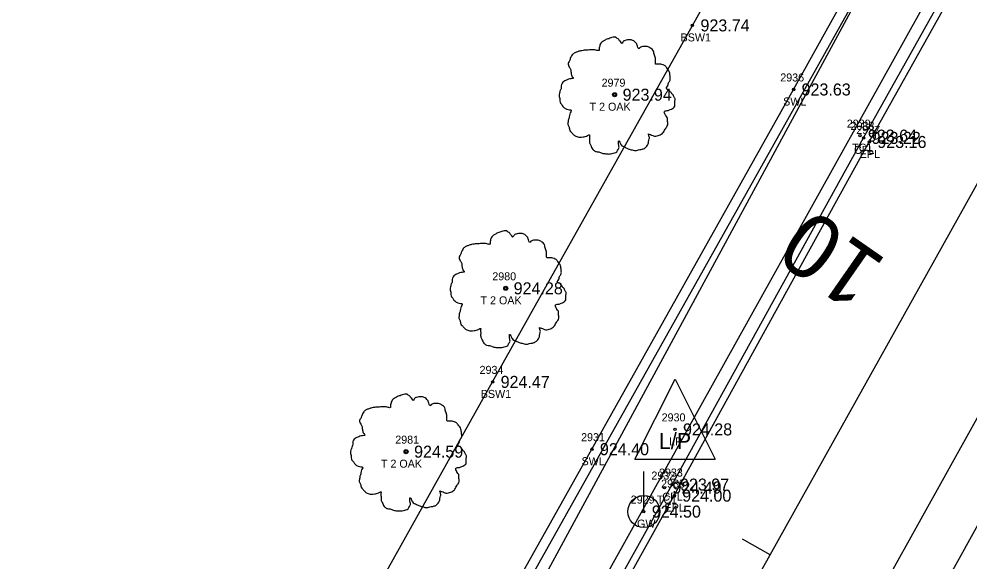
# Model space of a CAD drawing. Extents: x 1575382 to 1578175, y 1099175 to 1101955.
# Drawn here: x 1576923.3 to 1577042, y 1100636.3 to 1100704 of the extents above; entities that cross this region are included whole.
import ezdxf

# ---------------------------------------------------------------- set-up
doc = ezdxf.new("R2010")
doc.units = 0
for name, color, linetype in [('RD_EX_Conc', 7, 'Continuous'), ('RD_EX_Conc_txCode', 7, 'Continuous'), ('RD_EX_Road', 7, 'Continuous'), ('RD_EX_Road_txCode', 7, 'Continuous'), ('RD_EX_TX_Conc_ELEV', 7, 'Continuous'), ('RD_EX_TX_Road_ELEV', 7, 'Continuous'), ('RD_EX_TX_UT_ELEV', 7, 'Continuous'), ('RD_EX_TX_VEG_ELEV', 7, 'Continuous'), ('RD_EX_UT', 7, 'Continuous'), ('RD_EX_UT_txCode', 7, 'Continuous'), ('RD_EX_VEG', 7, 'Continuous'), ('RD_EX_VEG_txCode', 7, 'Continuous'), ('RD_HC_Cl', 7, 'Continuous'), ('RD_HC_Data_Tic', 7, 'Continuous'), ('RD_HC_TX_Sta50', 7, 'Continuous'), ('RD_SMD_Locator', 7, 'Continuous')]:
    doc.layers.add(name, color=color, linetype=linetype)

msp = doc.modelspace()

# ---------------------------------------------------------------- linework, layer by layer
at = {"layer": 'RD_EX_Conc'}
for points in [[(1576915.51, 1100485.43), (1576931.67, 1100514.72), (1576963.55, 1100571.7), (1576980.25, 1100601.73), (1577004.87, 1100645.93), (1577028.8, 1100689.21), (1577055.24, 1100736.45), (1577057.45, 1100744.79), (1577058.3, 1100753.83), (1577056.52, 1100760.31), (1577053.21, 1100754.37)], [(1576891.15, 1100493), (1576919.81, 1100523.92), (1576927.44, 1100533.74), (1576954.89, 1100579.32), (1576970.59, 1100607.1), (1576994.86, 1100650.35), (1577020.05, 1100695.25), (1577043.02, 1100736.52), (1577053.21, 1100754.37)], [(1576877.92, 1100500.23), (1576907.33, 1100532.14), (1576916.05, 1100543.22), (1576941.93, 1100586.45), (1576957.84, 1100614.79), (1576982.46, 1100658.75), (1577007.42, 1100703.25), (1577021.88, 1100729.08)], [(1576925.28, 1100434.6), (1576931.32, 1100441.65), (1576943.72, 1100456.06), (1576959.8, 1100485.15), (1576962.79, 1100490.55), (1576976.91, 1100516.3), (1576979.99, 1100521.81), (1576994.08, 1100547.41), (1577013.9, 1100582.65), (1577028.01, 1100607.52), (1577031.93, 1100618.57), (1577033.8, 1100624.22), (1577052.4, 1100657.66), (1577055.15, 1100662.64), (1577085.17, 1100716.01)]]:
    msp.add_lwpolyline(points, dxfattribs=at)
at = {"layer": 'RD_EX_Road'}
for points in [[(1576898.13, 1100449.6), (1576900.3, 1100453.32), (1576908.44, 1100470.19), (1576911.63, 1100476.81), (1576915.14, 1100482.86), (1576932.49, 1100514.03), (1576964.32, 1100571.23), (1576981.09, 1100601.29), (1577005.14, 1100644.55), (1577029.51, 1100688.7), (1577055.93, 1100735.94), (1577058.21, 1100744.65), (1577059.15, 1100754.07), (1577057.45, 1100760.72), (1577053.13, 1100767.88), (1577044.53, 1100776.69), (1577044.53, 1100776.69), (1577000.54, 1100813.12), (1576959.68, 1100843.4), (1576921.64, 1100879.47), (1576887.69, 1100919.8), (1576859.54, 1100961.84), (1576835.4, 1101008.92), (1576817.26, 1101055.71)], [(1576918.43, 1100436.45), (1576919.69, 1100438.1), (1576919.21, 1100438.45), (1576924.62, 1100446.41), (1576935.15, 1100461.4), (1576954.41, 1100495.42), (1576968.8, 1100521.52), (1576985.92, 1100552.3), (1577005.62, 1100587.42), (1577028.14, 1100627.58), (1577046.67, 1100660.87), (1577078.76, 1100718.33)]]:
    msp.add_lwpolyline(points, dxfattribs=at)
at = {"layer": 'RD_EX_UT'}
for p, q in [((1577000.24, 1100649.1), (1577005.24, 1100659.1)), ((1577005.24, 1100659.1), (1577010.24, 1100649.1)), ((1577000.24, 1100649.1), (1577010.24, 1100649.1)), ((1577001.34, 1100642.56), (1577001.34, 1100647.56))]:
    msp.add_line(p, q, dxfattribs=at)
msp.add_lwpolyline([(1576697.98, 1101074.32), (1577079.49, 1100801.52), (1576931.93, 1100529.3), (1577183.5, 1100413.67)], dxfattribs=at)
msp.add_circle((1577001.34, 1100642.56), 2, dxfattribs=at)
at = {"layer": 'RD_EX_VEG'}
msp.add_lwpolyline([(1576914.19, 1100486.82), (1576910.45, 1100488.95), (1576907.96, 1100484.96), (1576892.65, 1100493.17), (1576920.35, 1100523.24), (1576956.05, 1100578.76), (1577056.18, 1100757.22), (1577053.86, 1100737.22), (1576914.19, 1100486.82)], dxfattribs=at)
for centre, radius in [((1576997.7, 1100694.6), 0.25), ((1576997.69, 1100694.58), 0.0001), ((1576984.09, 1100670.43), 0.25), ((1576984.07, 1100670.41), 0.0001), ((1576971.65, 1100650.04), 0.25), ((1576971.63, 1100650.02), 0.0001)]:
    msp.add_circle(centre, radius, dxfattribs=at)
for points in [[(1576997.83, 1100701.77), (1576997.53, 1100701.79), (1576997.21, 1100701.69), (1576996.96, 1100701.59), (1576996.73, 1100701.52), (1576996.51, 1100701.42), (1576996.21, 1100701.24), (1576995.98, 1100701.04), (1576995.86, 1100700.79), (1576995.81, 1100700.57), (1576995.76, 1100700.3), (1576995.76, 1100700.12), (1576995.63, 1100700.1), (1576995.48, 1100700.12), (1576995.23, 1100700.2), (1576994.98, 1100700.2), (1576994.73, 1100700.2), (1576994.38, 1100700.17), (1576994.03, 1100700.17), (1576993.76, 1100700.12), (1576993.43, 1100700.07), (1576993.06, 1100699.95), (1576992.71, 1100699.82), (1576992.41, 1100699.57), (1576992.16, 1100699.1), (1576992.04, 1100698.75), (1576991.89, 1100698.5), (1576992.04, 1100698.05), (1576992.21, 1100697.7), (1576992.24, 1100697.5), (1576992.31, 1100697.07), (1576992.41, 1100696.85), (1576992.54, 1100696.65), (1576992.46, 1100696.62), (1576992.09, 1100696.57), (1576991.79, 1100696.47), (1576991.36, 1100696.25), (1576991.14, 1100696.02), (1576991.04, 1100695.7), (1576991.01, 1100695.35), (1576990.91, 1100695.15), (1576990.84, 1100694.87), (1576990.81, 1100694.8), (1576990.76, 1100694.47), (1576990.86, 1100694.02), (1576990.89, 1100693.67), (1576991.01, 1100693.45), (1576991.16, 1100693.27), (1576991.34, 1100693.02), (1576991.74, 1100692.8), (1576992.06, 1100692.7), (1576992.26, 1100692.67), (1576992.09, 1100692.17), (1576992.04, 1100691.82), (1576991.91, 1100691.42), (1576991.91, 1100691.35), (1576991.86, 1100690.87), (1576992.01, 1100690.55), (1576992.09, 1100690.17), (1576992.26, 1100689.95), (1576992.54, 1100689.65), (1576992.86, 1100689.42), (1576993.36, 1100689.3), (1576993.76, 1100689.32), (1576994.33, 1100689.5), (1576994.58, 1100689.57), (1576994.56, 1100689.4), (1576994.58, 1100689.02), (1576994.58, 1100688.6), (1576994.73, 1100688.28), (1576994.83, 1100688), (1576994.98, 1100687.75), (1576995.31, 1100687.53), (1576995.71, 1100687.45), (1576996.13, 1100687.3), (1576996.58, 1100687.23), (1576997.08, 1100687.2), (1576997.68, 1100687.35), (1576997.96, 1100687.48), (1576998.06, 1100687.65), (1576998.26, 1100688.03), (1576998.21, 1100688.25), (1576998.23, 1100688.85), (1576998.33, 1100688.68), (1576998.51, 1100688.33), (1576999.01, 1100688.03), (1576999.41, 1100687.85), (1576999.88, 1100687.7), (1577000.18, 1100687.63), (1577000.66, 1100687.7), (1577001.03, 1100687.78), (1577001.41, 1100687.9), (1577001.71, 1100688.18), (1577001.88, 1100688.45), (1577001.93, 1100688.73), (1577002.01, 1100689.1), (1577002.06, 1100689.27)], [(1577002.06, 1100689.27), (1577001.98, 1100689.45), (1577001.93, 1100689.7), (1577002.01, 1100689.67), (1577002.18, 1100689.62), (1577002.46, 1100689.5), (1577002.68, 1100689.42), (1577003.01, 1100689.45), (1577003.28, 1100689.55), (1577003.73, 1100689.82), (1577004.01, 1100690.3), (1577004.28, 1100690.7), (1577004.35, 1100691.02), (1577004.3, 1100691.25), (1577004.28, 1100691.75), (1577004.08, 1100692), (1577004.03, 1100692.12), (1577003.93, 1100692.52), (1577004.01, 1100692.57), (1577004.28, 1100692.62), (1577004.65, 1100692.75), (1577004.93, 1100692.87), (1577005.15, 1100693.05), (1577005.23, 1100693.27), (1577005.2, 1100693.67), (1577005.25, 1100694.07), (1577005.18, 1100694.22), (1577005.08, 1100694.37), (1577005, 1100694.57), (1577004.85, 1100694.72), (1577004.75, 1100694.87), (1577004.65, 1100694.97), (1577004.53, 1100695.12), (1577004.35, 1100695.25), (1577004.2, 1100695.3), (1577004.15, 1100695.45), (1577004.3, 1100695.65), (1577004.35, 1100695.75), (1577004.38, 1100695.97), (1577004.6, 1100696.32), (1577004.65, 1100696.72), (1577004.6, 1100697.15), (1577004.55, 1100697.42), (1577004.4, 1100697.7), (1577004.2, 1100697.95), (1577004.08, 1100698.12), (1577003.91, 1100698.25), (1577003.58, 1100698.37), (1577003.33, 1100698.42), (1577002.98, 1100698.42), (1577002.78, 1100698.47), (1577002.81, 1100698.52), (1577002.81, 1100698.67), (1577002.81, 1100698.95), (1577002.73, 1100699.4), (1577002.58, 1100699.9), (1577002.58, 1100699.92), (1577002.48, 1100700.17), (1577002.26, 1100700.37), (1577002.08, 1100700.47), (1577001.88, 1100700.59), (1577001.63, 1100700.62), (1577001.33, 1100700.62), (1577001.06, 1100700.57), (1577000.86, 1100700.47), (1577000.68, 1100700.35), (1577000.61, 1100700.49), (1577000.51, 1100700.79), (1577000.46, 1100700.94), (1577000.31, 1100701.12), (1577000.08, 1100701.32), (1576999.63, 1100701.44), (1576999.01, 1100701.37), (1576998.71, 1100701.17), (1576998.56, 1100700.99), (1576998.51, 1100701.12), (1576998.31, 1100701.32), (1576998.21, 1100701.49), (1576998.03, 1100701.62), (1576997.88, 1100701.72), (1576997.78, 1100701.77)], [(1576984.22, 1100677.6), (1576983.92, 1100677.62), (1576983.59, 1100677.52), (1576983.34, 1100677.42), (1576983.12, 1100677.35), (1576982.89, 1100677.25), (1576982.59, 1100677.07), (1576982.37, 1100676.87), (1576982.24, 1100676.62), (1576982.19, 1100676.4), (1576982.14, 1100676.12), (1576982.14, 1100675.95), (1576982.02, 1100675.92), (1576981.87, 1100675.95), (1576981.62, 1100676.02), (1576981.37, 1100676.02), (1576981.12, 1100676.02), (1576980.77, 1100676), (1576980.42, 1100676), (1576980.15, 1100675.95), (1576979.82, 1100675.9), (1576979.45, 1100675.77), (1576979.1, 1100675.65), (1576978.8, 1100675.4), (1576978.55, 1100674.92), (1576978.42, 1100674.57), (1576978.27, 1100674.32), (1576978.42, 1100673.87), (1576978.6, 1100673.52), (1576978.62, 1100673.32), (1576978.7, 1100672.9), (1576978.8, 1100672.67), (1576978.92, 1100672.47), (1576978.85, 1100672.45), (1576978.47, 1100672.4), (1576978.17, 1100672.3), (1576977.75, 1100672.08), (1576977.52, 1100671.85), (1576977.42, 1100671.53), (1576977.4, 1100671.18), (1576977.3, 1100670.98), (1576977.22, 1100670.7), (1576977.2, 1100670.63), (1576977.15, 1100670.3), (1576977.25, 1100669.85), (1576977.27, 1100669.5), (1576977.4, 1100669.28), (1576977.55, 1100669.1), (1576977.72, 1100668.85), (1576978.12, 1100668.63), (1576978.45, 1100668.53), (1576978.65, 1100668.5), (1576978.47, 1100668), (1576978.42, 1100667.65), (1576978.3, 1100667.25), (1576978.3, 1100667.18), (1576978.25, 1100666.7), (1576978.4, 1100666.38), (1576978.47, 1100666), (1576978.65, 1100665.78), (1576978.92, 1100665.48), (1576979.25, 1100665.25), (1576979.75, 1100665.13), (1576980.15, 1100665.15), (1576980.72, 1100665.33), (1576980.97, 1100665.4), (1576980.95, 1100665.23), (1576980.97, 1100664.85), (1576980.97, 1100664.43), (1576981.12, 1100664.1), (1576981.22, 1100663.83), (1576981.37, 1100663.58), (1576981.7, 1100663.35), (1576982.09, 1100663.28), (1576982.52, 1100663.13), (1576982.97, 1100663.05), (1576983.47, 1100663.03), (1576984.07, 1100663.18), (1576984.34, 1100663.3), (1576984.44, 1100663.48), (1576984.64, 1100663.85), (1576984.59, 1100664.08), (1576984.62, 1100664.68), (1576984.72, 1100664.5), (1576984.89, 1100664.15), (1576985.39, 1100663.85), (1576985.79, 1100663.68), (1576986.27, 1100663.53), (1576986.57, 1100663.45), (1576987.04, 1100663.53), (1576987.42, 1100663.6), (1576987.79, 1100663.73), (1576988.09, 1100664), (1576988.27, 1100664.28), (1576988.32, 1100664.55), (1576988.39, 1100664.93), (1576988.44, 1100665.1)], [(1576988.44, 1100665.1), (1576988.37, 1100665.28), (1576988.32, 1100665.53), (1576988.39, 1100665.5), (1576988.57, 1100665.45), (1576988.84, 1100665.33), (1576989.07, 1100665.25), (1576989.39, 1100665.28), (1576989.67, 1100665.38), (1576990.12, 1100665.65), (1576990.39, 1100666.13), (1576990.67, 1100666.53), (1576990.74, 1100666.85), (1576990.69, 1100667.08), (1576990.67, 1100667.58), (1576990.47, 1100667.83), (1576990.42, 1100667.95), (1576990.32, 1100668.35), (1576990.39, 1100668.4), (1576990.67, 1100668.45), (1576991.04, 1100668.58), (1576991.32, 1100668.7), (1576991.54, 1100668.88), (1576991.62, 1100669.1), (1576991.59, 1100669.5), (1576991.64, 1100669.9), (1576991.57, 1100670.05), (1576991.47, 1100670.2), (1576991.39, 1100670.4), (1576991.24, 1100670.55), (1576991.14, 1100670.7), (1576991.04, 1100670.8), (1576990.92, 1100670.95), (1576990.74, 1100671.08), (1576990.59, 1100671.13), (1576990.54, 1100671.28), (1576990.69, 1100671.48), (1576990.74, 1100671.58), (1576990.77, 1100671.8), (1576990.99, 1100672.15), (1576991.04, 1100672.55), (1576990.99, 1100672.97), (1576990.94, 1100673.25), (1576990.79, 1100673.52), (1576990.59, 1100673.77), (1576990.47, 1100673.95), (1576990.29, 1100674.07), (1576989.97, 1100674.2), (1576989.72, 1100674.25), (1576989.37, 1100674.25), (1576989.17, 1100674.3), (1576989.19, 1100674.35), (1576989.19, 1100674.5), (1576989.19, 1100674.77), (1576989.12, 1100675.22), (1576988.97, 1100675.72), (1576988.97, 1100675.75), (1576988.87, 1100676), (1576988.64, 1100676.2), (1576988.47, 1100676.3), (1576988.27, 1100676.42), (1576988.02, 1100676.45), (1576987.72, 1100676.45), (1576987.44, 1100676.4), (1576987.24, 1100676.3), (1576987.07, 1100676.17), (1576986.99, 1100676.32), (1576986.89, 1100676.62), (1576986.84, 1100676.77), (1576986.69, 1100676.95), (1576986.47, 1100677.15), (1576986.02, 1100677.27), (1576985.39, 1100677.2), (1576985.09, 1100677), (1576984.94, 1100676.82), (1576984.89, 1100676.95), (1576984.69, 1100677.15), (1576984.59, 1100677.32), (1576984.42, 1100677.45), (1576984.27, 1100677.55), (1576984.17, 1100677.6)], [(1576971.78, 1100657.21), (1576971.48, 1100657.23), (1576971.15, 1100657.13), (1576970.9, 1100657.03), (1576970.68, 1100656.96), (1576970.45, 1100656.86), (1576970.15, 1100656.68), (1576969.93, 1100656.48), (1576969.8, 1100656.23), (1576969.75, 1100656.01), (1576969.7, 1100655.73), (1576969.7, 1100655.56), (1576969.58, 1100655.53), (1576969.43, 1100655.56), (1576969.18, 1100655.63), (1576968.93, 1100655.63), (1576968.68, 1100655.63), (1576968.33, 1100655.61), (1576967.98, 1100655.61), (1576967.71, 1100655.56), (1576967.38, 1100655.51), (1576967.01, 1100655.38), (1576966.66, 1100655.26), (1576966.36, 1100655.01), (1576966.11, 1100654.53), (1576965.98, 1100654.18), (1576965.83, 1100653.93), (1576965.98, 1100653.48), (1576966.16, 1100653.13), (1576966.18, 1100652.93), (1576966.26, 1100652.51), (1576966.36, 1100652.29), (1576966.48, 1100652.09), (1576966.41, 1100652.06), (1576966.03, 1100652.01), (1576965.73, 1100651.91), (1576965.31, 1100651.69), (1576965.08, 1100651.46), (1576964.98, 1100651.14), (1576964.96, 1100650.79), (1576964.86, 1100650.59), (1576964.78, 1100650.31), (1576964.76, 1100650.24), (1576964.71, 1100649.91), (1576964.81, 1100649.46), (1576964.83, 1100649.11), (1576964.96, 1100648.89), (1576965.11, 1100648.71), (1576965.28, 1100648.46), (1576965.68, 1100648.24), (1576966.01, 1100648.14), (1576966.21, 1100648.11), (1576966.03, 1100647.61), (1576965.98, 1100647.26), (1576965.86, 1100646.86), (1576965.86, 1100646.79), (1576965.81, 1100646.31), (1576965.96, 1100645.99), (1576966.03, 1100645.61), (1576966.21, 1100645.39), (1576966.48, 1100645.09), (1576966.81, 1100644.86), (1576967.31, 1100644.74), (1576967.71, 1100644.76), (1576968.28, 1100644.94), (1576968.53, 1100645.01), (1576968.5, 1100644.84), (1576968.53, 1100644.46), (1576968.53, 1100644.04), (1576968.68, 1100643.71), (1576968.78, 1100643.44), (1576968.93, 1100643.19), (1576969.25, 1100642.96), (1576969.65, 1100642.89), (1576970.08, 1100642.74), (1576970.53, 1100642.66), (1576971.03, 1100642.64), (1576971.63, 1100642.79), (1576971.9, 1100642.91), (1576972, 1100643.09), (1576972.2, 1100643.46), (1576972.15, 1100643.69), (1576972.18, 1100644.29), (1576972.28, 1100644.11), (1576972.45, 1100643.76), (1576972.95, 1100643.46), (1576973.35, 1100643.29), (1576973.83, 1100643.14), (1576974.13, 1100643.06), (1576974.6, 1100643.14), (1576974.98, 1100643.21), (1576975.35, 1100643.34), (1576975.65, 1100643.61), (1576975.83, 1100643.89), (1576975.88, 1100644.16), (1576975.95, 1100644.54), (1576976, 1100644.71)], [(1576976, 1100644.71), (1576975.93, 1100644.89), (1576975.88, 1100645.14), (1576975.95, 1100645.11), (1576976.13, 1100645.06), (1576976.4, 1100644.94), (1576976.63, 1100644.86), (1576976.95, 1100644.89), (1576977.23, 1100644.99), (1576977.68, 1100645.26), (1576977.95, 1100645.74), (1576978.23, 1100646.14), (1576978.3, 1100646.46), (1576978.25, 1100646.69), (1576978.23, 1100647.19), (1576978.03, 1100647.44), (1576977.98, 1100647.56), (1576977.88, 1100647.96), (1576977.95, 1100648.01), (1576978.23, 1100648.06), (1576978.6, 1100648.19), (1576978.88, 1100648.31), (1576979.1, 1100648.49), (1576979.17, 1100648.71), (1576979.15, 1100649.11), (1576979.2, 1100649.51), (1576979.13, 1100649.66), (1576979.03, 1100649.81), (1576978.95, 1100650.01), (1576978.8, 1100650.16), (1576978.7, 1100650.31), (1576978.6, 1100650.41), (1576978.48, 1100650.56), (1576978.3, 1100650.69), (1576978.15, 1100650.74), (1576978.1, 1100650.89), (1576978.25, 1100651.09), (1576978.3, 1100651.19), (1576978.33, 1100651.41), (1576978.55, 1100651.76), (1576978.6, 1100652.16), (1576978.55, 1100652.59), (1576978.5, 1100652.86), (1576978.35, 1100653.13), (1576978.15, 1100653.38), (1576978.03, 1100653.56), (1576977.85, 1100653.68), (1576977.53, 1100653.81), (1576977.28, 1100653.86), (1576976.93, 1100653.86), (1576976.73, 1100653.91), (1576976.75, 1100653.96), (1576976.75, 1100654.11), (1576976.75, 1100654.38), (1576976.68, 1100654.83), (1576976.53, 1100655.33), (1576976.53, 1100655.36), (1576976.43, 1100655.61), (1576976.2, 1100655.81), (1576976.03, 1100655.91), (1576975.83, 1100656.03), (1576975.58, 1100656.06), (1576975.28, 1100656.06), (1576975, 1100656.01), (1576974.8, 1100655.91), (1576974.63, 1100655.78), (1576974.55, 1100655.93), (1576974.45, 1100656.23), (1576974.4, 1100656.38), (1576974.25, 1100656.56), (1576974.03, 1100656.76), (1576973.58, 1100656.88), (1576972.95, 1100656.81), (1576972.65, 1100656.61), (1576972.5, 1100656.43), (1576972.45, 1100656.56), (1576972.25, 1100656.76), (1576972.15, 1100656.93), (1576971.98, 1100657.06), (1576971.83, 1100657.16), (1576971.73, 1100657.21)]]:
    msp.add_spline(points, degree=3, dxfattribs=at)
at = {"layer": 'RD_HC_Cl'}
msp.add_line((1576888.29, 1100406.32), (1577092.18, 1100771.63), dxfattribs=at)
at = {"layer": 'RD_HC_Data_Tic'}
msp.add_line((1577017.14, 1100637.18), (1577013.65, 1100639.13), dxfattribs=at)
at = {"layer": 'RD_SMD_Locator'}
for centre in [(1577007.42, 1100703.25), (1577020.05, 1100695.25), (1576997.7, 1100694.6), (1577028.33, 1100689.49), (1577028.8, 1100689.21), (1577029.51, 1100688.7), (1576984.09, 1100670.43), (1576982.46, 1100658.75), (1577005.24, 1100652.82), (1576971.65, 1100650.04), (1576994.86, 1100650.35), (1577003.92, 1100645.56), (1577004.87, 1100645.93), (1577005.14, 1100644.55), (1577001.34, 1100642.56)]:
    msp.add_circle(centre, 0.15, dxfattribs=at)

# ---------------------------------------------------------------- texts
at = {"layer": 'RD_EX_Conc_txCode'}
for s, p in [('BSW1', (1577005.94, 1100701.25)), ('2936', (1577018.39, 1100696.25)), ('SWL', (1577018.75, 1100693.25)), ('2939', (1577026.7, 1100690.49)), ('2938', (1577027.17, 1100690.21)), ('TC1', (1577027.37, 1100687.49)), ('CFL', (1577027.6, 1100687.21)), ('2934', (1576980.83, 1100659.75)), ('BSW1', (1576980.98, 1100656.75)), ('2931', (1576993.51, 1100651.35)), ('SWL', (1576993.57, 1100648.35)), ('2932', (1577002.29, 1100646.56)), ('2933', (1577003.24, 1100646.93)), ('TC1', (1577002.96, 1100643.56)), ('CFL', (1577003.66, 1100643.93))]:
    msp.add_text(s, height=1, dxfattribs=at).set_placement(p)
at = {"layer": 'RD_EX_Road_txCode'}
for s, p in [('2937', (1577027.88, 1100689.7)), ('EPL', (1577028.31, 1100686.7)), ('2935', (1577003.51, 1100645.55)), ('EPL', (1577003.94, 1100642.55))]:
    msp.add_text(s, height=1, dxfattribs=at).set_placement(p)
at = {"layer": 'RD_EX_TX_Conc_ELEV'}
for s, p in [('923.74', (1577008.42, 1100702.5)), ('923.63', (1577021.05, 1100694.5)), ('923.64', (1577029.33, 1100688.74)), ('923.22', (1577029.8, 1100688.46)), ('924.47', (1576983.46, 1100658)), ('924.40', (1576995.86, 1100649.6)), ('924.49', (1577004.92, 1100644.81)), ('923.97', (1577005.87, 1100645.18))]:
    msp.add_text(s, height=1.5, dxfattribs=at).set_placement(p)
at = {"layer": 'RD_EX_TX_Road_ELEV'}
for s, p in [('923.16', (1577030.51, 1100687.95)), ('924.00', (1577006.14, 1100643.8))]:
    msp.add_text(s, height=1.5, dxfattribs=at).set_placement(p)
at = {"layer": 'RD_EX_TX_UT_ELEV'}
for s, p in [('924.28', (1577006.24, 1100652.07)), ('924.50', (1577002.34, 1100641.81))]:
    msp.add_text(s, height=1.5, dxfattribs=at).set_placement(p)
at = {"layer": 'RD_EX_TX_VEG_ELEV'}
for s, p in [('923.94', (1576998.7, 1100693.85)), ('924.28', (1576985.09, 1100669.68)), ('924.59', (1576972.65, 1100649.29))]:
    msp.add_text(s, height=1.5, dxfattribs=at).set_placement(p)
at = {"layer": 'RD_EX_UT'}
msp.add_text('L/P', height=2, dxfattribs=at).set_placement((1577003.23, 1100650.38))
at = {"layer": 'RD_EX_UT_txCode'}
for s, p in [('2930', (1577003.57, 1100653.82)), ('LP', (1577004.49, 1100650.82)), ('2929', (1576999.71, 1100643.56)), ('GW', (1577000.5, 1100640.56))]:
    msp.add_text(s, height=1, dxfattribs=at).set_placement(p)
at = {"layer": 'RD_EX_VEG_txCode'}
for s, p in [('2979', (1576996.07, 1100695.6)), ('T 2 OAK', (1576994.57, 1100692.6)), ('2980', (1576982.42, 1100671.43)), ('T 2 OAK', (1576980.95, 1100668.43)), ('2981', (1576970.3, 1100651.04)), ('T 2 OAK', (1576968.51, 1100648.04))]:
    msp.add_text(s, height=1, dxfattribs=at).set_placement(p)
at = {"layer": 'RD_HC_TX_Sta50'}
msp.add_text('10', height=8, rotation=145.1317, dxfattribs=at).set_placement((1577031.91, 1100673.83))

doc.saveas('drawing.dxf')
